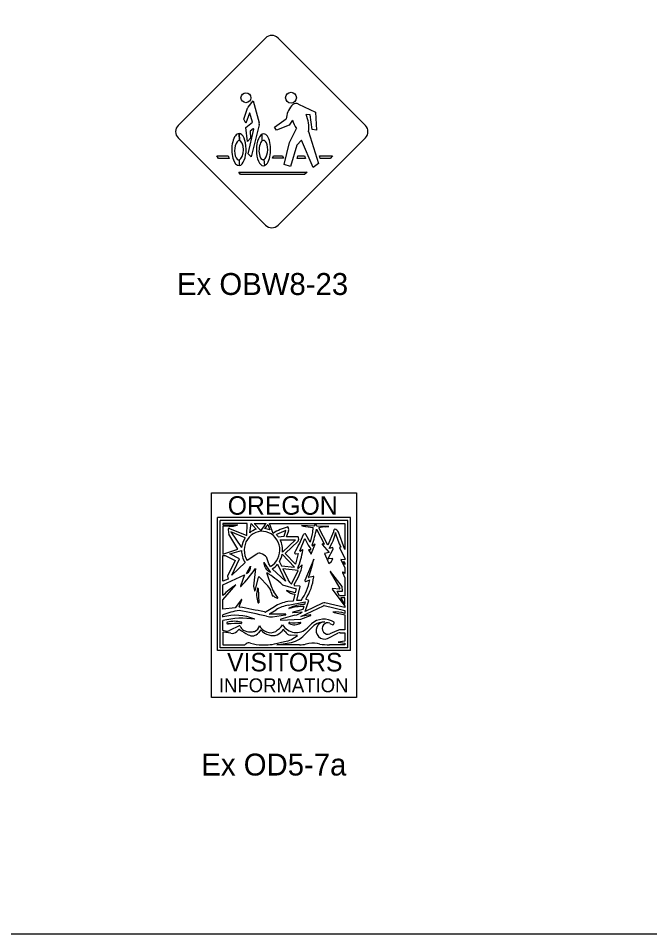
# Model space of a CAD drawing. Extents: x 42133 to 45533, y 41351 to 47951.
# Drawn here: x 43376.5 to 43592.4, y 46901.4 to 47214.5 of the extents above; entities that cross this region are included whole.
import ezdxf

# ---------------------------------------------------------------- set-up
doc = ezdxf.new("R2010")
doc.units = 0
doc.layers.add('P_ODOT_PLAN_Border', color=7, linetype='Continuous')
doc.layers.add('P_TRAF_SIGN_SignDetails', color=7, linetype='Continuous')

msp = doc.modelspace()

# ---------------------------------------------------------------- linework, layer by layer
at = {"layer": 'P_ODOT_PLAN_Border'}
msp.add_lwpolyline([(42208.34, 46901.35), (43808.34, 46901.35), (43808.34, 47901.35), (42208.34, 47901.35)], close=True, dxfattribs=at)
at = {"layer": 'P_TRAF_SIGN_SignDetails'}
for p, q in [((43431.21, 47177.82), (43461.1, 47207.7)), ((43465.35, 47207.7), (43495.23, 47177.82)), ((43455.11, 47184.09), (43456.87, 47186.24)), ((43456.87, 47186.24), (43458.95, 47178.66)), ((43453.6, 47179.92), (43454.88, 47183.68)), ((43472.37, 47185.11), (43472.37, 47185.11)), ((43472.37, 47185.11), (43472.37, 47185.11)), ((43472.37, 47185.11), (43478.16, 47182.35)), ((43478.16, 47182.35), (43478.46, 47176.15)), ((43454.31, 47178.54), (43453.6, 47179.92)), ((43455.55, 47181.99), (43454.31, 47178.54)), ((43456.58, 47178.88), (43455.7, 47181.98)), ((43464.18, 47177.22), (43468.14, 47180.07)), ((43470.27, 47179.64), (43469.11, 47177.86)), ((43476.33, 47181.43), (43474.93, 47181.53)), ((43476.97, 47176.41), (43476.33, 47181.43)), ((43454.38, 47177.07), (43456.58, 47178.88)), ((43454.9, 47172.29), (43454.38, 47177.07)), ((43455.18, 47168.07), (43457.05, 47176.5)), ((43456.86, 47176.62), (43455.81, 47175.8)), ((43458.95, 47177.98), (43456.21, 47167.1)), ((43464.88, 47176.17), (43464.18, 47177.22)), ((43469.11, 47177.86), (43464.88, 47176.17)), ((43469.25, 47171.97), (43471.64, 47176.76)), ((43478.46, 47176.15), (43476.97, 47176.41)), ((43461.09, 47143.69), (43431.22, 47173.57)), ((43452.12, 47172.62), (43452.04, 47175.02)), ((43452.04, 47175.02), (43452.12, 47172.62)), ((43455.97, 47173.41), (43454.9, 47172.29)), ((43455.81, 47175.8), (43455.97, 47173.41)), ((43459.91, 47172.49), (43459.88, 47174.82)), ((43459.91, 47172.49), (43459.88, 47174.82)), ((43495.23, 47173.57), (43465.35, 47143.68)), ((43475.75, 47175.69), (43479.17, 47164.8)), ((43467.43, 47164.41), (43469.25, 47171.97)), ((43471.81, 47171.12), (43469.67, 47163.76)), ((43473.34, 47172.75), (43471.81, 47171.12)), ((43477.38, 47163.43), (43473.34, 47172.75)), ((43444.97, 47166.56), (43444.43, 47167.42)), ((43444.43, 47167.42), (43448.28, 47167.42)), ((43448.28, 47167.42), (43448.65, 47166.56)), ((43456.21, 47167.1), (43455.18, 47168.07)), ((43463.47, 47166.57), (43463.78, 47167.43)), ((43463.78, 47167.43), (43466.87, 47167.43)), ((43466.87, 47167.43), (43467.24, 47166.57)), ((43471.87, 47166.56), (43472.11, 47167.42)), ((43472.11, 47167.42), (43474.37, 47167.42)), ((43474.37, 47167.42), (43474.74, 47166.56)), ((43479.53, 47167.42), (43483.98, 47167.42)), ((43479.8, 47166.56), (43479.53, 47167.42)), ((43483.98, 47167.42), (43483.22, 47166.56)), ((43448.65, 47166.56), (43444.97, 47166.56)), ((43452.12, 47164.09), (43452.13, 47166.06)), ((43460.81, 47164.12), (43460.61, 47166.18)), ((43467.24, 47166.57), (43463.47, 47166.57)), ((43469.67, 47163.76), (43467.43, 47164.41)), ((43474.74, 47166.56), (43471.87, 47166.56)), ((43479.17, 47164.8), (43477.38, 47163.43)), ((43483.22, 47166.56), (43479.8, 47166.56)), ((43451.96, 47161.88), (43475.31, 47161.88)), ((43452.5, 47161.02), (43451.96, 47161.88)), ((43474.45, 47161.02), (43452.5, 47161.02)), ((43475.31, 47161.88), (43474.45, 47161.02)), ((43442.59, 47052.15), (43492.24, 47052.15)), ((43442.59, 46982.14), (43442.59, 47052.15)), ((43492.24, 47052.15), (43492.24, 46982.14)), ((43490.1, 47043.66), (43444.62, 47043.66)), ((43444.62, 46998.18), (43444.62, 47043.66)), ((43490.1, 47043.66), (43444.62, 47043.66)), ((43489.18, 47042.69), (43445.55, 47042.69)), ((43445.55, 46999.16), (43445.55, 47042.69)), ((43454.83, 47041.71), (43446.48, 47041.71)), ((43446.48, 47041.71), (43446.48, 47041.22)), ((43454.73, 47037.56), (43454.83, 47041.71)), ((43455.68, 47038.51), (43456.22, 47041.71)), ((43456.22, 47041.71), (43457.89, 47039.68)), ((43459.47, 47039.27), (43457.15, 47041.71)), ((43457.15, 47041.71), (43461.33, 47041.71)), ((43463.65, 47038.28), (43462.49, 47041.71)), ((43462.49, 47041.71), (43488.25, 47041.71)), ((43488.25, 47041.71), (43488.25, 47032.78)), ((43489.18, 46999.16), (43489.18, 47042.69)), ((43490.1, 46998.18), (43490.1, 47043.66)), ((43446.48, 47041.22), (43451.58, 47041.23)), ((43448.69, 47040.73), (43446.48, 47040.73)), ((43446.48, 47040.73), (43446.48, 47031.2)), ((43448.79, 47040), (43454.73, 47037.56)), ((43449.23, 47038.77), (43452.9, 47033.49)), ((43454.09, 47036.77), (43449.23, 47038.77)), ((43461.9, 47041.27), (43462.52, 47039.44)), ((43467.41, 47037.38), (43468.01, 47039.25)), ((43468.01, 47039.25), (43468.01, 47039.25)), ((43468.29, 47037.07), (43468.99, 47039.27)), ((43477.57, 47040.8), (43473.4, 47040.97)), ((43474.72, 47040.64), (43477.35, 47040.25)), ((43477.89, 47041.25), (43477.57, 47040.8)), ((43478.73, 47040.73), (43478.24, 47041.27)), ((43478.5, 47039.76), (43481.13, 47034.68)), ((43482.68, 47040.68), (43478.73, 47040.73)), ((43482.4, 47034.27), (43479.32, 47040.22)), ((43481.75, 47040.49), (43482.68, 47040.68)), ((43484.28, 47038.83), (43482.4, 47034.27)), ((43484.84, 47037.8), (43485, 47038.53)), ((43488.25, 47032.78), (43486.04, 47038.66)), ((43451.58, 47032.91), (43448.56, 47038.04)), ((43465.44, 47037.11), (43467.41, 47037.38)), ((43466.07, 47036.09), (43471.36, 47036.09)), ((43471.36, 47036.09), (43466.89, 47031.87)), ((43467.83, 47031.45), (43472.23, 47035.6)), ((43472.23, 47037.07), (43468.29, 47037.07)), ((43472.86, 47032.34), (43474.56, 47036.58)), ((43476.33, 47035.33), (43474.89, 47037.92)), ((43477.08, 47038.08), (43476.33, 47035.33)), ((43446.48, 47031.2), (43451.58, 47032.91)), ((43448.92, 47031.25), (43452.85, 47032.46)), ((43473.7, 47032.7), (43473.04, 47032.19)), ((43476.35, 47032.66), (43475.72, 47032.66)), ((43475.72, 47032.66), (43476.64, 47031.2)), ((43478.04, 47034.62), (43477.17, 47034.07)), ((43480.45, 47034.48), (43482.8, 47031.69)), ((43480.99, 47034.5), (43480.58, 47034.68)), ((43482.55, 47029.7), (43484.17, 47032.9)), ((43482.8, 47033.15), (43483.82, 47035.03)), ((43484.07, 47033.4), (43482.8, 47033.15)), ((43484.17, 47032.9), (43484.07, 47033.4)), ((43486.86, 47033.54), (43486.39, 47033.4)), ((43486.39, 47033.4), (43488.25, 47029.73)), ((43446.48, 47021.9), (43446.48, 47030.71)), ((43446.48, 47030.71), (43447.33, 47030.71)), ((43447.33, 47030.71), (43450.65, 47029)), ((43450.65, 47029), (43448.1, 47023.61)), ((43452.22, 47029.55), (43448.92, 47031.25)), ((43449.55, 47023.94), (43452.22, 47029.55)), ((43458.08, 47031.2), (43454.82, 47028.97)), ((43462.2, 47027.84), (43461.56, 47029.97)), ((43471.03, 47026.68), (43466.79, 47031.15)), ((43466.79, 47031.15), (43466.79, 47031.15)), ((43471.31, 47027.77), (43467.83, 47031.45)), ((43472.23, 47031.45), (43471.31, 47027.77)), ((43471.36, 47031.33), (43472.23, 47031.45)), ((43477.58, 47029.48), (43474.55, 47022.19)), ((43482.8, 47031.69), (43481.29, 47031.45)), ((43481.29, 47031.45), (43482.68, 47028.02)), ((43484.07, 47029.73), (43482.67, 47029.52)), ((43488.25, 47029.24), (43486.86, 47029.36)), ((43486.86, 47029.36), (43488.25, 47026.54)), ((43488.25, 47029.73), (43488.25, 47029.24)), ((43454.11, 47028.34), (43449.55, 47023.94)), ((43454.6, 47024.59), (43455.99, 47027.04)), ((43455.99, 47027.04), (43455.74, 47025.75)), ((43457.62, 47026.3), (43456.92, 47020.2)), ((43460.46, 47028.32), (43462.77, 47024.88)), ((43460.95, 47026.77), (43460.46, 47028.32)), ((43462.82, 47026.93), (43462.2, 47027.84)), ((43467.92, 47021.95), (43463.39, 47026.14)), ((43465.19, 47027.7), (43467.92, 47021.95)), ((43465.19, 47027.7), (43465.19, 47027.7)), ((43465.81, 47028.58), (43466.48, 47027.15)), ((43466.48, 47027.15), (43471.03, 47026.68)), ((43472.25, 47025.57), (43466.98, 47026.12)), ((43466.98, 47026.12), (43468.76, 47022.39)), ((43473.63, 47027.53), (43472.22, 47026.25)), ((43488.25, 47027.61), (43487.75, 47028.63)), ((43487.78, 47028.65), (43488.25, 47028.1)), ((43488.25, 47028.1), (43488.25, 47027.61)), ((43488.25, 47026.54), (43488.25, 47024.59)), ((43446.48, 47020.68), (43453.9, 47024.1)), ((43448.33, 47022.64), (43446.48, 47021.9)), ((43448.1, 47023.61), (43448.33, 47022.64)), ((43453.9, 47024.1), (43452.48, 47020.26)), ((43457.5, 47018.69), (43458.67, 47023.21)), ((43459.06, 47023.31), (43461.85, 47020.38)), ((43463.18, 47019.73), (43461.56, 47024.84)), ((43469.91, 47020.92), (43472.25, 47025.57)), ((43477.41, 47023.57), (43475.94, 47023.19)), ((43483.2, 47025.16), (43486.48, 47019.46)), ((43487.32, 47020.08), (43483.31, 47025.24)), ((43487.41, 47024.88), (43488.25, 47023.13)), ((43488.25, 47024.59), (43487.51, 47024.99)), ((43488.25, 47023.13), (43488.25, 47016.89)), ((43446.48, 47015.55), (43450.89, 47020.68)), ((43446.48, 47017.02), (43446.48, 47020.68)), ((43456.92, 47020.2), (43457.27, 47018.69)), ((43458.54, 47019.46), (43458.78, 47014.57)), ((43466.9, 47020.68), (43471.54, 47019.33)), ((43472.8, 47020.2), (43471.03, 47020.39)), ((43471.77, 47015.3), (43472.9, 47020.06)), ((43474.84, 47021.86), (43476.18, 47022.39)), ((43483.96, 47019.46), (43483.84, 47019.21)), ((43486.35, 47019.24), (43483.96, 47019.46)), ((43487.45, 47018.48), (43487.32, 47020.08)), ((43463.04, 47018.21), (43463.42, 47016.77)), ((43465.29, 47016.36), (43463.88, 47018.34)), ((43464.24, 47016.48), (43465.16, 47016.17)), ((43471.21, 47017.97), (43468.29, 47018.72)), ((43471.09, 47017.45), (43470.52, 47015.06)), ((43471.54, 47019.33), (43471.21, 47017.97)), ((43483.84, 47019.21), (43488.25, 47013.34)), ((43486.39, 47016.89), (43485.53, 47018.37)), ((43485.59, 47018.48), (43487.45, 47018.48)), ((43488.25, 47016.89), (43486.39, 47016.89)), ((43446.48, 47012.37), (43446.48, 47015.55)), ((43452.9, 47015.65), (43450.65, 47012.86)), ((43452.06, 47013.29), (43453.01, 47015.58)), ((43464.11, 47013.19), (43461.32, 47011.5)), ((43470.52, 47015.06), (43468.65, 47014.93)), ((43468.85, 47013.73), (43474.67, 47014.81)), ((43473.21, 47015.3), (43471.77, 47015.3)), ((43473.16, 47009.8), (43480.95, 47013.54)), ((43474.17, 47013.22), (43473.86, 47012.24)), ((43474.67, 47014.81), (43474.4, 47013.96)), ((43474.61, 47011.57), (43475.84, 47015.3)), ((43480.57, 47014.43), (43474.61, 47011.57)), ((43475.84, 47015.3), (43474.83, 47015.79)), ((43481.17, 47013.56), (43488.25, 47011.88)), ((43488.25, 47012.88), (43481.37, 47014.51)), ((43486.81, 47016.17), (43487.99, 47014.15)), ((43488.25, 47016.28), (43486.87, 47016.28)), ((43488.25, 47014.23), (43488.25, 47016.28)), ((43488.25, 47013.34), (43488.25, 47012.88)), ((43450.65, 47012.86), (43446.48, 47012.37)), ((43446.48, 47009.67), (43446.48, 47010.4)), ((43462.48, 47010.8), (43464.69, 47012.13)), ((43462.52, 47010.65), (43462.48, 47010.8)), ((43467.92, 47010.65), (43462.52, 47010.65)), ((43463.48, 47009.7), (43467.94, 47010.37)), ((43471.11, 47010.25), (43466.26, 47008.89)), ((43473.86, 47012.24), (43470.4, 47011.34)), ((43470.43, 47011.19), (43473.63, 47011.39)), ((43476.43, 47010.4), (43473.16, 47009.8)), ((43473.16, 47008.89), (43476.49, 47010.17)), ((43488.25, 47011.88), (43488.25, 47010.9)), ((43488.25, 47010.41), (43488.25, 47005.28)), ((43446.48, 47005.03), (43446.48, 47008.45)), ((43448.08, 47007.9), (43448.08, 47007.9)), ((43448.08, 47007.9), (43448.08, 47007.9)), ((43461.45, 47009.96), (43461.45, 47009.96)), ((43466.3, 47008.65), (43473.16, 47008.89)), ((43483.1, 47007.51), (43484.08, 47006.99)), ((43484.5, 47007.86), (43483.63, 47008.33)), ((43447.42, 47004.88), (43446.48, 47005.03)), ((43446.48, 47004.26), (43446.48, 47000.14)), ((43449.17, 47004.11), (43446.74, 47004.5)), ((43452.06, 47006.64), (43448.71, 47005.06)), ((43449.17, 47004.11), (43449.17, 47004.11)), ((43451.92, 47005.39), (43451.26, 47004.7)), ((43459.47, 47005.28), (43458.68, 47004.28)), ((43467.78, 47004.66), (43467.14, 47005.51)), ((43474.44, 47003.56), (43476.64, 47005.89)), ((43475.98, 47006.57), (43475.38, 47005.94)), ((43482.28, 47002.36), (43485.85, 47004.11)), ((43485.46, 47004.99), (43483.07, 47003.93)), ((43488.25, 47005.28), (43486.64, 47005.28)), ((43486.64, 47004.29), (43488.25, 47004.29)), ((43488.25, 47004.29), (43488.25, 47001.36)), ((43464.09, 47000.46), (43467.6, 47001.24)), ((43464.89, 47000.14), (43469.21, 47000.8)), ((43472, 47003.32), (43469.63, 47003.44)), ((43488.25, 47001.36), (43485.93, 47001.12)), ((43485.93, 47001.12), (43488.25, 47000.75)), ((43488.25, 47000.75), (43488.25, 47000.14)), ((43490.1, 46998.18), (43444.62, 46998.18)), ((43489.18, 46999.16), (43445.55, 46999.16)), ((43446.48, 47000.14), (43453.45, 47000.13)), ((43459.94, 47000.14), (43461.2, 47000.14)), ((43472.64, 47000.14), (43464.89, 47000.14)), ((43479.69, 47000.44), (43478.84, 47000.6)), ((43488.25, 47000.14), (43482.91, 47000.14)), ((43492.24, 46982.14), (43442.59, 46982.14))]:
    msp.add_line(p, q, dxfattribs=at)
for centre, radius in [((43454.38, 47187.29), 1.7), ((43469.79, 47187.29), 1.85)]:
    msp.add_circle(centre, radius, dxfattribs=at)
for centre, radius, start, end in [((43463.22, 47205.57), 3.01, 45.0123, 135), ((43463.22, 47205.57), 3.01, 45.0123, 135), ((43456.14, 47183.24), 1.33, 140.7953, 161.0848), ((43476.6, 47179.21), 8.5, 141.4976, 174.1516), ((43472.45, 47182.78), 3.04, 133.0399, 145.5045), ((43471.46, 47183.48), 1.87, 60.6785, 125.4757), ((43455.62, 47181.96), 0.0825, 15.7926, 160.2668), ((43494.73, 47189.41), 26.34, 201.7818, 208.7113), ((43466.37, 47177.34), 9.53, 349.9861, 26.0599), ((43433.34, 47175.69), 3.01, 135, 225.0172), ((43456.93, 47176.52), 0.12, 347.4969, 128.222), ((43457.66, 47178.31), 1.33, 345.8354, 15.3004), ((43493.1, 47175.69), 3.01, 315, 44.9762), ((43463.22, 47145.81), 3.01, 224.9829, 315)]:
    msp.add_arc(centre, radius, start, end, dxfattribs=at)
for centre, major_axis, ratio, start_param, end_param in [((43451.98, 47169.55), (0.07, 5.48), 0.449594, 0, 3.226449), ((43451.98, 47169.55), (0.07, 5.48), 0.449594, 3.226449, 6.283185), ((43460.39, 47169.49), (0.07, 5.48), 0.441082, 0.239911, 3.343374), ((43460.39, 47169.49), (0.07, 5.48), 0.441082, 3.343374, 6.523097), ((43460.32, 47169.38), (0.11, 3.3), 0.450132, 3.408447, 6.635031), ((43452.01, 47169.32), (0.11, 3.3), 0.450132, 0, 3.29422), ((43452.01, 47169.32), (0.11, 3.3), 0.450132, 3.29422, 6.283185), ((43460.32, 47169.38), (0.11, 3.3), 0.450132, 0.351846, 3.408447), ((43469.41, 47032.9), (0, 12.25), 0.948983, 0.767926, 1.024184), ((43452.05, 47039.41), (0, 3.92), 0.948983, 1.479235, 1.926314), ((43448.62, 47039.78), (0, 0.289), 0.948983, 5.590301, 7.894387), ((43449.25, 47046.67), (0, -5.96), 0.948983, 6.182903, 6.707041), ((43459.88, 47032.57), (0, 6.43), 0.948983, 3.643657, 8.44764), ((43459.88, 47032.57), (0, 7.41), 0.948983, 0.287599, 0.640516), ((43469.41, 47032.9), (0, 11.52), 0.948983, 0.756959, 0.914749), ((43459.88, 47032.57), (0, 7.41), 0.948983, 5.898808, 6.160459), ((43473.88, 47019.7), (0, 21.49), 0.948983, 0.254026, 0.525465), ((43473.88, 47019.7), (0, 20.51), 0.948983, 0.306603, 0.484296), ((43467.29, 47039.55), (0, -1.81), 0.948983, 1.412931, 2.120652), ((43475.41, 47046.73), (0, -6.13), 0.948983, 5.929904, 6.165333), ((43444.26, 47047.1), (0, -36.82), 0.948983, 1.213437, 1.370117), ((43470.26, 47040.09), (0, -7.47), 0.948983, 1.298133, 1.591226), ((43478.07, 47041.1), (0, 0.245), 0.948983, 5.480892, 7.209628), ((43481.62, 47029.25), (0, 11.24), 0.948983, 6.271318, 6.501216), ((43486.34, 47038.21), (0, 2.27), 0.948983, 0.819938, 1.291294), ((43483.88, 47037.25), (0, 2.68), 0.948983, 5.267026, 5.927886), ((43503.47, 47043.27), (0, -20.04), 0.948983, 4.951253, 5.21987), ((43459.88, 47032.57), (0, 7.41), 0.948983, 0.967679, 1.446928), ((43459.88, 47032.57), (0, 7.41), 0.948983, 5.372569, 5.505763), ((43459.88, 47032.57), (0, 7.41), 0.948983, 4.617518, 5.207188), ((43417.95, 47064.12), (0, -64.69), 0.948983, 1.045694, 1.152752), ((43471.17, 47036.33), (0, -1.34), 0.948983, 0.991794, 2.149799), ((43474.49, 47037.66), (0, 0.489), 0.948983, 5.245271, 7.455558), ((43484.2, 47040.21), (0, -10.79), 0.948983, 5.055559, 5.435041), ((43475.78, 47039.92), (0, -9.78), 0.948983, 1.047308, 1.352492), ((43459.88, 47032.57), (0, 7.41), 0.948983, 1.586192, 2.178805), ((43436.24, 47041.05), (0, -40.56), 0.948983, 1.19952, 1.359899), ((43472.97, 47032.29), (0, 0.122), 0.948983, 1.172127, 3.770389), ((43473.76, 47032.6), (0, 0.122), 0.948983, 4.417619, 6.911842), ((43476.34, 47032.91), (0, -0.245), 0.948983, 0, 2.293448), ((43456.89, 47042.15), (0, -23.52), 0.948983, 1.086641, 1.245169), ((43477.1, 47034.17), (0, -0.122), 0.948983, 4.35503, 6.823605), ((43480.54, 47034.56), (0, -0.122), 0.948983, 2.761401, 5.436773), ((43481.03, 47034.62), (0, -0.122), 0.948983, 5.902679, 8.353018), ((43458.96, 47030.13), (0, 1.42), 0.948983, 5.895145, 7.001522), ((43458.04, 47026.8), (0, 4.88), 0.948983, 5.420666, 5.969699), ((43459.88, 47032.57), (0, 7.41), 0.948983, 4.143269, 4.520318), ((43471.24, 47031.53), (0, -0.232), 0.948983, 3.9907, 6.847866), ((43440.57, 47038), (0, -39.91), 0.948983, 1.194834, 1.355732), ((43482.66, 47029.64), (0, 0.122), 0.948983, 1.083848, 3.283117), ((43481.99, 47030.12), (0, -2.22), 0.948983, 0.330778, 1.393562), ((43415.02, 47058.85), (0, -55.44), 0.948983, 0.797603, 0.943535), ((43453.62, 47026.87), (0, -2.5), 0.948983, 0.42591, 1.104739), ((43463.15, 47027.54), (0, 2.45), 0.948983, 1.892445, 2.578154), ((43459.88, 47032.57), (0, 7.41), 0.948983, 3.663733, 3.995679), ((43458.45, 47030.44), (0, -16.25), 0.948983, 0.934594, 1.390811), ((43472.17, 47026.31), (0, -0.0734), 0.948983, 4.341113, 6.991812), ((43487.77, 47028.64), (0, 0.0245), 0.948983, 5.437444, 8.335084), ((43458.89, 47023.15), (0, 0.245), 0.948983, 5.497787, 7.587875), ((43437.09, 46984.07), (0, 48.24), 0.948983, 5.574118, 5.719232), ((43437.09, 46984.07), (0, 48.97), 0.948983, 5.697659, 5.719746), ((43460.86, 47025.67), (0, -17.74), 0.948983, 0.979974, 1.444655), ((43475.91, 47023.3), (0, -0.122), 0.948983, 4.336427, 6.528164), ((43477.44, 47023.46), (0, -0.122), 0.948983, 1.444655, 3.386571), ((43483.26, 47025.2), (0, -0.0734), 0.948983, 2.255317, 5.257994), ((43487.48, 47024.92), (0, -0.0734), 0.948983, 2.677945, 5.176424), ((43469.03, 46991.68), (0, 34.74), 0.948983, 0.58298, 0.753599), ((43452.59, 47020.21), (0, -0.122), 0.948983, 4.341498, 7.080789), ((43458.43, 47019.41), (0, 0.133), 0.948983, 5.103465, 7.760998), ((43458.57, 47016.92), (0, 4.89), 0.948983, 4.978457, 5.497787), ((43467.58, 47021.28), (0, -4.89), 0.948983, 5.034289, 5.359162), ((43472.97, 47024.85), (0, -5.08), 0.948983, 5.218003, 5.596251), ((43471.05, 47020.64), (0, -0.245), 0.948983, 4.076187, 6.183646), ((43472.79, 47020.09), (0, 0.122), 0.948983, 4.467151, 6.183628), ((43460.54, 47025.44), (0, -16.76), 0.948983, 0.9213, 1.3882), ((43474.76, 47022.09), (0, 0.245), 0.948983, 1.158431, 3.500436), ((43486.36, 47019.39), (0, -0.147), 0.948983, 6.196383, 8.399746), ((43457.39, 47018.72), (0, -0.122), 0.948983, 4.957235, 7.587412), ((43465.47, 47017.33), (0, 7.84), 0.948983, 1.300951, 1.928012), ((43463.61, 47015.92), (0, 0.872), 0.948983, 5.408616, 6.516503), ((43465.19, 47016.29), (0, 0.122), 0.948983, 2.826777, 5.359699), ((43471.52, 47022.54), (0, -5.11), 0.948983, 5.555593, 6.194057), ((43485.59, 47018.41), (0, 0.0734), 0.948983, 0, 2.122628), ((43452.19, 47013.23), (0, 0.147), 0.948983, 1.157277, 2.969964), ((43452.95, 47015.6), (0, 0.0734), 0.948983, 4.298922, 7.151703), ((43458.64, 47014.64), (0, -0.156), 0.948983, 5.016265, 7.392242), ((43471.07, 47000.49), (0, 14.67), 0.948983, 0.174535, 0.523639), ((43471.07, 47000.49), (0, 13.45), 0.948983, 0.174535, 0.523639), ((43474.9, 46998.46), (0, 15.51), 0.948983, 0.033623, 0.405596), ((43473.55, 46996.66), (0, 16.58), 0.948983, 6.243696, 6.567174), ((43481.09, 47013.21), (0, 1.34), 0.948983, 6.060898, 6.711157), ((43481.09, 47013.21), (0, 0.367), 0.948983, 6.060898, 6.711157), ((43486.87, 47016.21), (0, 0.0734), 0.948983, 0, 2.122371), ((43488.11, 47014.23), (0, -0.147), 0.948983, 5.264058, 7.853982), ((43455.51, 46984.74), (0, 27.37), 0.948983, 0.133673, 0.355147), ((43450.82, 46991.5), (0, 18.75), 0.948983, 5.905493, 6.530001), ((43405.55, 46729.7), (0, 286.39), 0.948983, 6.076022, 6.111269), ((43405.55, 46729.7), (0, 287.62), 0.948983, 6.07985, 6.111557), ((43460.86, 47012.35), (0, 0.978), 0.948983, 2.938258, 3.665065), ((43462.52, 47010.73), (0, 0.0734), 0.948983, 0.523984, 3.141593), ((43467.92, 47010.51), (0, 0.147), 0.948983, 3.281269, 6.283185), ((43469.12, 47012.64), (0, 0.0734), 0.948983, 0.486494, 3.425581), ((43470.42, 47011.26), (0, -0.0734), 0.948983, 3.386571, 6.342042), ((43468.91, 47019.33), (0, -9.37), 0.948983, 0.249356, 0.559429), ((43476.45, 47010.29), (0, 0.122), 0.948983, 3.490606, 6.457635), ((43484.92, 46999.4), (0, 12.02), 0.948983, 5.987317, 6.357739), ((43492.58, 47041.35), (0, -31.27), 0.948983, 5.992351, 6.136682), ((43453.09, 46978.85), (0, 30.41), 0.948983, 6.133745, 6.514283), ((43448.17, 47007.59), (0, 0.322), 0.948983, 0.295256, 3.436272), ((43450.47, 46997.23), (0, 10.97), 0.948983, 6.057312, 6.514943), ((43461.46, 46737.05), (0, 270.6), 0.948983, 0.034139, 0.051445), ((43452.76, 47007.69), (0, 0.223), 0.948983, 2.809617, 6.120758), ((43463.62, 47019.74), (0, -10.04), 0.948983, 6.053166, 6.268013), ((43459.02, 47013.53), (0, -10.56), 0.948983, 0.588306, 0.904657), ((43466.29, 47008.77), (0, 0.122), 0.948983, 0.261861, 3.176501), ((43471.57, 47010.22), (0, 5.87), 0.948983, 2.149325, 3.895523), ((43469.21, 47007.64), (0, 0.211), 0.948983, 5.537761, 9.438543), ((43471.03, 47011.8), (0, -4.77), 0.948983, 5.869705, 6.747308), ((43471, 47024.82), (0, -17.11), 0.948983, 6.181187, 6.40773), ((43473.03, 47007.68), (0, 0.156), 0.948983, 3.390643, 6.337237), ((43480.97, 47001.8), (0, 7.11), 0.948983, 5.877977, 7.118356), ((43481.31, 47001.13), (0, 6.85), 0.948983, 0.001103, 0.801888), ((43481.16, 47005.04), (0, 2.93), 0.948983, 6.231063, 9.838851), ((43482.35, 47005.73), (0, 1.96), 0.948983, 5.862773, 9.825222), ((43483.84, 47007.67), (0, 0.722), 0.948983, 3.49205, 4.980462), ((43446.71, 47004.26), (0, -0.245), 0.948983, 2.990709, 4.712389), ((43447.77, 47007.3), (0, -2.45), 0.948983, 6.132405, 6.702225), ((43449.68, 47006.5), (0, 2.45), 0.948983, 2.919863, 3.891011), ((43452.08, 47005.21), (0, 0.245), 0.948983, 5.759874, 7.068583), ((43452.16, 47006.41), (0, 0.245), 0.948983, 5.142916, 6.702033), ((43464.3, 47023.92), (0, -22.47), 0.948983, 5.679479, 5.839715), ((43454.9, 47007.74), (0, 2.93), 0.948983, 2.001324, 2.641211), ((43455.7, 47009.27), (0, -4.69), 0.948983, 5.781631, 6.325414), ((43456.55, 47006.17), (0, -2.93), 0.948983, 5.759603, 7.155941), ((43456.12, 47009.67), (0, -5.08), 0.948983, 6.235762, 6.526778), ((43456.74, 47007.08), (0, -2.41), 0.948983, 0.236694, 1.447046), ((43462.77, 47008.71), (0, 4.4), 0.948983, 2.024785, 3.592161), ((43463.61, 47009.26), (0, -5.91), 0.948983, 5.453317, 6.032588), ((43463.53, 47007.72), (0, 4.4), 0.948983, 2.822755, 4.186902), ((43470.07, 47006.33), (0, 2.93), 0.948983, 2.17608, 2.98158), ((43486.64, 47002.34), (0, 2.93), 0.948983, 0, 0.437314), ((43486.64, 47002.34), (0, 1.96), 0.948983, 0, 0.437314), ((43455.33, 46999.41), (0, 1.47), 0.948983, 5.839613, 7.013276), ((43459.62, 47013.08), (0, -12.95), 0.948983, 5.978056, 6.30874), ((43465.21, 47013.1), (0, -12.12), 0.948983, 0.209012, 0.631188), ((43467.87, 47010.48), (0, -9.78), 0.948983, 0.144178, 0.785398), ((43477.22, 46990.96), (0, -9.78), 0.948983, 2.966965, 3.390884), ((43453.48, 47001.59), (0, 1.47), 0.948983, 3.120406, 3.872228), ((43461.2, 47014.81), (0, -14.67), 0.948983, 0, 0.209609), ((43472.64, 47009.92), (0, -9.78), 0.948983, 0, 0.249291), ((43482.91, 47019.7), (0, -19.56), 0.948983, 6.108769, 6.283185)]:
    msp.add_ellipse(centre, major_axis=major_axis, ratio=ratio, start_param=start_param, end_param=end_param, dxfattribs=at)

# ---------------------------------------------------------------- texts
for s, height, p in [('Ex OBW8-23', 7.5, (43430.81, 47119.83)), ('OREGON', 6.322, (43448.16, 47044.66)), ('VISITORS', 6.322, (43447.93, 46991.07)), ('INFORMATION', 4.7357, (43445.11, 46983.94)), ('Ex OD5-7a', 7.5, (43439.13, 46955.45))]:
    msp.add_text(s, height=height, dxfattribs=at).set_placement(p)

doc.saveas('drawing.dxf')
